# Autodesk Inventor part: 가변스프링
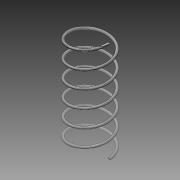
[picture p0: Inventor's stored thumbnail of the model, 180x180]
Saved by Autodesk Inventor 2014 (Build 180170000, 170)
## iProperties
Created: 2016-11
Part Number: 가변스프링
Material: 강철, 탄소
Document SubType Name: Modeling
Designer: NET
Density: 7.87 g/cm^3
Appearance: 반연마
Mass: 14.838 g
Surface Area: 38.0532 cm^2
Volume: 1.88539 cm^3
Author: NET
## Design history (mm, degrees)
feature "코일2" pitch "d15" = 10; turns "d17" = 6; dims "d16" = 84.36759 (= d2), "d18" = 0, angle "d19" = 90 deg, angle "d20" = 90 deg, "d21" = 0, "d22" = 0
sketch "스케치4"
  geometry: L1 (-17, 0)-(-15, 0) reference; 1 further point
  constraints: 1 horizontal alignment
extrude "돌출3" cut sketch "스케치4" distance "d23" = 10; taper "d24" = 0 deg
node "작업 평면2"
sketch "스케치5"
  geometry: L1 (-15, 0)-(-17, 0) reference; 1 further point
  constraints: 1 horizontal alignment
extrude "돌출4" cut sketch "스케치5" distance "d25" = 10; taper "d26" = 0 deg
node "솔리드2"
sketch "스케치1"
  geometry: L1 (0, 0)-(16, 0); L2 (16, 0)-(16, 84.368); L3 (16, 84.368)-(0, 84.368); L4 (0, 84.368)-(0, 0); C1 r 1 at (16, 0)
  constraints: 8 end point, 2 parallel, 1 centre point, 1 coincident, 1 horizontal, 1 perpendicular
  dimensions: "d0" = 32 diameter of L2 L4; "d1" = 2 diameter of C1; "d2" = 84.36759 distance between parallel lines of L1 L3 (derived)
node "절단 모서리 투영3"
node "절단 모서리 투영4"
